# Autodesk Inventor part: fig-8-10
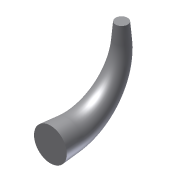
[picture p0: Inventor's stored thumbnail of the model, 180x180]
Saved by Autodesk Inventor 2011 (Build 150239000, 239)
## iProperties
Shininess: 77.0
Length Units: 11269
Angle Units: 11279
Time Units: 11290
Mass Units: 11283
Length Display Precision: 3
Angle Display Precision: 2
Created: 2001-12
Part Number: fig-8-10
Document SubType Name: Modeling
Designer: CADSoft
Density: 1 g/cm^3
Density: 0.0
Volumn: 0.0
Area: 0.0
PropertySet Name: Model Information
Control State: 0
Master: False
Checked Out: False
Author: CADSoft
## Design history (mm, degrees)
sketch "Sketch6"
  geometry: L1 (-48.928, -34.062)-(-33.928, -34.062); L2 (16.072, 15.938)-(16.072, 30.938); A1 r 50 centre (-33.928, 15.938) between (-33.928, -34.062) and (16.072, 15.938)
  constraints: 4 end point, 2 point on circle, 2 tangent, 1 centre point, 1 horizontal, 1 perpendicular
  dimensions: "d4" = 15 distance of L1.start L1.end; "d5" = 15 distance of L2.start L2.end; "d6" = 50 radius of A1
workplane "Work Plane1"
sketch "Sketch7"
  geometry: C1 r 15 at (0, 0)
  constraints: 1 centre point
  dimensions: "d7" = 30 diameter of C1
sweep "Sweep7" sketch "Sketch7" dims "d13" = -5 deg
body "Solid1"
